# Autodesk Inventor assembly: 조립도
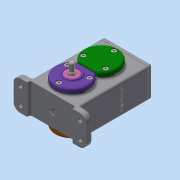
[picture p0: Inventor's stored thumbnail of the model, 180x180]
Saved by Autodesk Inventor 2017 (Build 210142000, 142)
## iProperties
Part Number: 조립도
Material: 일반
Document SubType Name: Assembly
Designer: 222
Author: 222
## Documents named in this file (24)
- C:\Users\222\Desktop\600506V1029\답안조립품.iam
- C:\Users\222\Desktop\600506V1029\본체.ipt
- C:\Users\222\Desktop\600506V1029\Ű 4 x 4 x 12.ipt
- C:\Users\222\Desktop\600506V1029\Ű 5 x 5 x 12.ipt
- C:\Users\222\Desktop\600506V1029\개스킷 A.ipt
- C:\Users\222\Desktop\600506V1029\개스킷 B.ipt
- C:\Users\222\Desktop\600506V1029\개스킷 C.ipt
- C:\Users\222\Desktop\600506V1029\베어링 6001.ipt
- 베어링 6001.ipt
- C:\Users\222\Desktop\600506V1029\베어링 6002.ipt
- 베어링 6002.ipt
- C:\Users\222\Desktop\600506V1029\볼트 M4.ipt
- C:\Users\222\Desktop\600506V1029\스퍼기어 A.ipt
- C:\Users\222\Desktop\600506V1029\스퍼기어 B.ipt
- C:\Users\222\Desktop\600506V1029\오일 실 10 20 7.ipt
- C:\Users\222\Desktop\600506V1029\오일 실 12 22 7.ipt
- C:\Users\222\Desktop\600506V1029\축 A.ipt
- C:\Users\222\Desktop\600506V1029\축 B.ipt
- C:\Users\222\Desktop\600506V1029\칼라.ipt
- C:\Users\222\Desktop\600506V1029\커버 A.ipt
- C:\Users\222\Desktop\600506V1029\커버 B.ipt
- C:\Users\222\Desktop\600506V1029\커버 C.ipt
- C:\Users\222\Desktop\600506V1029\커버 D.ipt
- C:\Users\222\Desktop\600506V1029\커버 E.ipt
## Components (7 placed, 5 different names)
1. Ű 4 x 4 x 12:1
2. Ű 5 x 5 x 12:1
3. 개스킷 A:1
4. 개스킷 B:1
5. 개스킷 C:1
6. 개스킷 B:2
7. 개스킷 B:3
